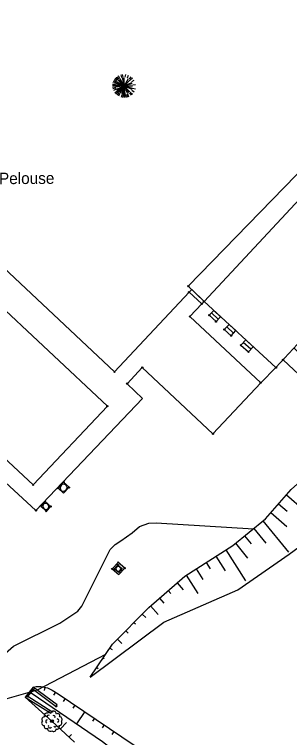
# Model space of a CAD drawing. Extents: x 344013 to 344423, y 298505 to 298795.
# Drawn here: x 344157.5 to 344180.9, y 298556.7 to 298618.3 of the extents above; entities that cross this region are included whole.
import ezdxf

# ---------------------------------------------------------------- set-up
doc = ezdxf.new("R2010")
doc.units = 0
for name, color, linetype in [('Default', 7, 'Continuous'), ('DH_CADRE -CARTOUCHE', 7, 'Continuous'), ('GO_MUR', 7, 'Continuous'), ('PC_CONCRETE', 7, 'Continuous'), ('PS_BOLT', 7, 'Continuous'), ('PS_CONST', 7, 'Continuous'), ('PS_DIM', 7, 'Continuous'), ('TOPO_COURBE NIVEAU', 7, 'Continuous'), ('TOPO_POINT', 7, 'Continuous'), ('TOPO_TALUS-TERRAIN NATUREL', 7, 'Continuous'), ('VOIRIE_ESPACE VERT', 7, 'Continuous')]:
    doc.layers.add(name, color=color, linetype=linetype)

# ---------------------------------------------------------------- blocks, each defined once
blk = doc.blocks.new('REG_INC')
at = {"layer": 'Default'}
for p, q in [((0, 1), (1, 1)), ((0, 0), (0, 1)), ((1, 1), (1, 0)), ((1, 0), (0, 0))]:
    blk.add_line(p, q, dxfattribs=at)
for centre, start, end in [((0.5, 0.498), 90.00577, 135.00577), ((0.5, 0.5), 45.00687, 90.00687), ((0.498, 0.5), 135.00554, 180.00554), ((0.501, 0.5), 180.00663, 225.00663), ((0.499, 0.498), 225.00686, 270.00686), ((0.499, 0.5), 270.00577, 315.00577), ((0.499, 0.499), 0.00663, 45.00663), ((0.501, 0.499), 315.00554, 0.00554)]:
    blk.add_arc(centre, 0.44, start, end, dxfattribs=at)
blk = doc.blocks.new('POINT_DISPLAY')
at = {"layer": 'Default'}
blk.add_circle((0, 0), 0.05, dxfattribs=at)
blk = doc.blocks.new('ARB1')
at = {"layer": 'Default'}
blk.add_circle((0, 0), 0.122, dxfattribs=at)
for centre, radius, start, end in [((-0.471, 0.503), 0.183, 53.95544, 222.20655), ((-0.153, 0.664), 0.211, 43.69255, 183.5969), ((0.139, 0.613), 0.241, 358.45835, 125.19284), ((0.501, 0.468), 0.183, 325.14445, 131.01755), ((-0.613, 0.139), 0.241, 88.45835, 215.19284), ((-0.373, -0.024), 0.149, 103.70924, 242.34652), ((-0.276, 0.37), 0.134, 52.43963, 209.54959), ((0.164, 0.38), 0.112, 330.58954, 133.71274), ((0.458, 0.052), 0.137, 276.62143, 88.96702), ((0.613, -0.139), 0.241, 268.45835, 35.19284), ((0.664, 0.153), 0.211, 313.69255, 93.5969), ((-0.664, -0.153), 0.211, 133.69255, 273.5969), ((-0.478, -0.443), 0.19, 155.22426, 300.93774), ((-0.139, -0.613), 0.241, 178.45835, 305.19284), ((-0.163, -0.42), 0.148, 159.53711, 338.16632), ((0.271, -0.38), 0.112, 210.58954, 13.71274), ((0.448, -0.483), 0.188, 243.13234, 33.02965), ((0.153, -0.664), 0.211, 223.69255, 3.5969)]:
    blk.add_arc(centre, radius, start, end, dxfattribs=at)
blk = doc.blocks.new('ARB2')
at = {"layer": 'Default'}
for p, q in [((-0.513, 0.525), (-0.688, 0.702)), ((-0.438, 0.589), (-0.588, 0.786)), ((-0.356, 0.642), (-0.481, 0.858)), ((-0.181, 0.716), (-0.244, 0.956)), ((-0.088, 0.736), (-0.119, 0.983)), ((0.106, 0.736), (0.144, 0.983)), ((0.287, 0.684), (0.388, 0.914)), ((0.456, 0.589), (0.612, 0.786)), ((0.531, 0.525), (0.706, 0.702)), ((-0.731, 0), (-0.981, 0)), ((-0.725, 0.1), (-0.969, 0.133)), ((-0.706, 0.195), (-0.944, 0.259)), ((-0.675, 0.286), (-0.9, 0.381)), ((-0.631, 0.373), (-0.844, 0.497)), ((-0.575, 0.453), (-0.775, 0.605)), ((0.65, 0.373), (0.862, 0.497)), ((0.744, 0.1), (0.987, 0.133)), ((-0.725, -0.1), (-0.969, -0.133)), ((-0.706, -0.195), (-0.944, -0.259)), ((-0.675, -0.287), (-0.9, -0.383)), ((-0.575, -0.455), (-0.775, -0.605)), ((-0.513, -0.527), (-0.688, -0.702)), ((-0.438, -0.591), (-0.588, -0.787)), ((0.456, -0.591), (0.612, -0.787)), ((0.531, -0.527), (0.706, -0.702)), ((0.65, -0.373), (0.862, -0.498)), ((0.725, -0.195), (0.963, -0.259)), ((-0.356, -0.644), (-0.481, -0.859)), ((-0.181, -0.717), (-0.244, -0.956)), ((-0.088, -0.737), (-0.119, -0.983)), ((0.013, -0.741), (0.013, -0.989)), ((0.106, -0.737), (0.144, -0.983)), ((0.2, -0.717), (0.263, -0.956)), ((0.287, -0.686), (0.388, -0.916))]:
    blk.add_line(p, q, dxfattribs=at)
for points in [[(-0.169, 0.677), (0.013, 0), (-0.6, 0.35)], [(0.013, 0.008), (0.013, 0), (-0.081, 0.695)], [(0.362, 0.608), (0.013, 0), (0.013, 0.702)], [(-0.487, -0.497), (0.013, 0), (-0.694, 0)], [(-0.688, 0.091), (0.013, 0), (-0.338, 0.608)], [(-0.638, -0.269), (0.013, 0), (-0.688, -0.092)], [(-0.487, 0.495), (0.013, 0), (-0.669, 0.181)], [(-0.419, 0.556), (0.013, 0), (-0.638, 0.269)], [(-0.169, -0.678), (0.013, 0), (-0.6, -0.352)], [(-0.544, -0.428), (0.013, 0), (-0.338, -0.608)], [(-0.081, -0.695), (0.013, 0), (-0.419, -0.558)], [(0.013, -0.702), (0.013, 0), (0, 0)], [(0.656, 0.269), (0.013, 0), (0.506, 0.495)], [(0.688, 0.181), (0.013, 0), (0.713, 0)], [(0.438, -0.558), (0.013, 0), (0.656, -0.269)], [(0.506, -0.497), (0.013, 0), (0.688, -0.181)], [(0.1, -0.695), (0.013, 0), (0.281, -0.648)], [(0.019, 0), (0.013, 0), (0.013, -0.009)]]:
    blk.add_lwpolyline(points, dxfattribs=at)

msp = doc.modelspace()

# ---------------------------------------------------------------- linework, layer by layer
at = {"layer": 'DH_CADRE -CARTOUCHE'}
for points in [[(344159.085, 298578.25), (344123.824, 298611.129), (344130.237, 298617.899), (344165.405, 298584.943)], [(344173.637, 298593.851), (344189.896, 298611.294), (344195.985, 298605.701), (344179.76, 298588.225)]]:
    msp.add_lwpolyline(points, close=True, dxfattribs=at)
at = {"layer": 'GO_MUR'}
msp.add_lwpolyline([(344160.686, 298558.935), (344158.641, 298560.224), (344159.117, 298560.832), (344161.054, 298559.39), (344161.144, 298559.51), (344159.089, 298561.039), (344158.42, 298560.186), (344160.606, 298558.808)], close=True, dxfattribs=at)
at = {"layer": 'PS_BOLT'}
for points in [[(344173.637, 298593.851), (344172.292, 298595.161), (344185.567, 298608.8), (344198.259, 298622.397), (344163.217, 298655.561), (344163.898, 298656.291), (344171.693, 298664.218), (344209.192, 298629.258), (344201.744, 298621.299), (344205.95, 298617.379), (344203.771, 298607.721), (344197.46, 298609.156), (344192.341, 298613.899), (344190.988, 298612.393), (344196.963, 298606.8), (344195.985, 298605.701)], [(344173.444, 298593.641), (344172.427, 298592.568), (344178.462, 298586.939), (344174.396, 298582.587), (344168.376, 298588.228), (344167.085, 298586.853), (344168.386, 298585.586), (344159.324, 298576.069), (344121.411, 298611.054), (344130.716, 298620.945), (344149.461, 298603.379), (344147.717, 298601.519)], [(344149.461, 298603.379), (344166.011, 298587.87), (344172.356, 298594.641)], [(344173.444, 298593.641), (344172.356, 298594.641)], [(344179.76, 298588.225), (344178.462, 298586.939), (344172.427, 298592.568), (344173.444, 298593.641), (344173.637, 298593.851)], [(344181.304, 298589.888), (344183.07, 298588.205), (344182.156, 298587.216), (344180.365, 298588.877)]]:
    msp.add_lwpolyline(points, dxfattribs=at)
msp.add_lwpolyline([(344166.885, 298571.16), (344166.324, 298571.64), (344165.819, 298571.088), (344166.38, 298570.609)], close=True, dxfattribs=at)
at = {"layer": 'PS_DIM'}
for points in [[(344172.585, 298594.876), (344172.356, 298594.641), (344173.444, 298593.641), (344173.637, 298593.851)], [(344175.045, 298592.557), (344174.66, 298592.137), (344174.086, 298592.684), (344174.462, 298593.093)], [(344175.763, 298591.898), (344175.363, 298591.462), (344175.943, 298590.936), (344176.339, 298591.368)], [(344177.19, 298590.587), (344176.772, 298590.132), (344177.42, 298589.564), (344177.824, 298590.004)]]:
    msp.add_lwpolyline(points, close=True, dxfattribs=at)
for points in [[(344174.852, 298592.347), (344174.274, 298592.889)], [(344176.141, 298591.152), (344175.563, 298591.68)], [(344177.622, 298589.784), (344176.981, 298590.359)]]:
    msp.add_lwpolyline(points, dxfattribs=at)
at = {"layer": 'TOPO_COURBE NIVEAU'}
for points in [[(344156.256, 298563.524), (344157.409, 298564.509), (344161.369, 298566.478), (344162.88, 298567.483), (344163.228, 298567.922), (344165.643, 298572.732), (344166.068, 298573.157), (344166.564, 298573.494), (344167.517, 298574.16), (344168.147, 298574.694), (344168.934, 298574.993), (344169.564, 298575.023), (344177.835, 298574.512)], [(344144.559, 298543.398), (344145.126, 298543.758), (344146.164, 298544.291), (344147.173, 298545.407), (344147.575, 298546.106), (344147.955, 298547.238), (344148.408, 298549.983), (344148.576, 298551.974), (344149.201, 298553.647), (344150.556, 298555.627), (344153.701, 298558.494), (344155.669, 298559.733), (344159.453, 298560.805), (344165.265, 298563.828)]]:
    msp.add_lwpolyline(points, dxfattribs=at)
at = {"layer": 'TOPO_TALUS-TERRAIN NATUREL'}
for p, q in [((344180.646, 298577.395), (344182.159, 298576.077)), ((344179.989, 298576.641), (344180.708, 298576.015)), ((344179.332, 298575.887), (344180.697, 298574.698)), ((344178.64, 298575.169), (344180.813, 298572.505)), ((344177.865, 298574.537), (344178.897, 298573.272)), ((344177.09, 298573.904), (344177.634, 298573.237)), ((344176.315, 298573.272), (344177.349, 298572.004)), ((344175.491, 298572.706), (344177.166, 298570.089)), ((344174.649, 298572.167), (344175.444, 298570.924)), ((344173.806, 298571.627), (344174.146, 298571.096)), ((344172.964, 298571.088), (344173.545, 298570.18)), ((344172.121, 298570.549), (344173.115, 298568.997)), ((344171.352, 298569.912), (344171.866, 298569.316)), ((344170.595, 298569.258), (344170.815, 298569.004)), ((344169.838, 298568.605), (344170.214, 298568.169)), ((344169.081, 298567.951), (344169.723, 298567.207)), ((344168.368, 298567.25), (344168.668, 298566.955)), ((344167.667, 298566.537), (344167.795, 298566.411)), ((344166.965, 298565.823), (344167.184, 298565.608)), ((344166.264, 298565.11), (344166.638, 298564.742)), ((344165.62, 298564.35), (344165.805, 298564.224)), ((344165.058, 298563.523), (344165.137, 298563.469)), ((344164.496, 298562.695), (344164.631, 298562.603)), ((344159.089, 298561.039), (344159.089, 298561.039)), ((344160.076, 298561.009), (344160.015, 298560.736)), ((344160.985, 298560.609), (344160.827, 298560.347)), ((344161.821, 298560.061), (344161.648, 298559.805)), ((344162.65, 298559.502), (344162.476, 298559.244)), ((344163.478, 298558.942), (344162.781, 298557.91)), ((344164.307, 298558.382), (344164.132, 298558.123)), ((344161.415, 298557.468), (344161.937, 298558.011)), ((344165.136, 298557.822), (344164.96, 298557.562)), ((344165.964, 298557.262), (344165.786, 298556.998)), ((344162.137, 298556.776), (344162.36, 298557.008))]:
    msp.add_line(p, q, dxfattribs=at)
for points in [[(344163.934, 298561.868), (344165.849, 298564.688), (344168.923, 298567.814), (344171.996, 298570.469), (344176.091, 298573.09), (344178.872, 298575.358), (344181.046, 298577.856), (344183.915, 298580.416), (344184.947, 298581.398), (344185.091, 298582.452), (344184.802, 298583.514), (344186.691, 298584.063), (344189.735, 298586.719), (344192.676, 298590.389), (344195.465, 298594.065), (344199.099, 298597.718), (344203.435, 298602.18), (344207.43, 298606.195), (344211.519, 298610.49), (344214.324, 298613.364), (344217.026, 298616.042), (344219.477, 298617.84), (344221.365, 298618.23), (344223.701, 298617.841)], [(344163.934, 298561.868), (344170.201, 298566.564), (344176.522, 298569.299), (344180.879, 298572.338), (344183.313, 298574.136), (344185.048, 298576.477), (344188.051, 298580.099), (344191.638, 298583.956), (344195.571, 298587.909), (344198.338, 298590.807), (344202.379, 298595.055), (344209.468, 298599.999), (344216.32, 298605.698), (344221.544, 298609.146), (344226.03, 298610.067), (344230.196, 298608.376), (344234.376, 298605.349), (344238.337, 298601.801), (344242.051, 298598.625), (344245.256, 298595.883), (344247.329, 298593.914), (344248.413, 298593.093)], [(344159.089, 298561.039), (344159.354, 298561.091), (344159.742, 298561.084), (344160.297, 298560.96), (344160.706, 298560.777), (344161.231, 298560.46), (344172.069, 298553.135), (344173.202, 298552.277), (344176.155, 298549.708), (344180.474, 298545.354), (344182.152, 298543.854), (344182.779, 298543.428), (344183.25, 298543.23), (344183.942, 298543.143), (344184.794, 298543.131), (344197.63, 298543.79), (344202.568, 298544.192), (344226.369, 298544.819)], [(344162.596, 298556.335), (344160.685, 298558.13), (344158.42, 298560.186)], [(344158.923, 298560.537), (344164.997, 298556.401), (344169.095, 298553.232), (344172.662, 298550.66), (344176.659, 298547.676), (344178.472, 298545.954), (344180.609, 298543.896), (344181.623, 298542.715), (344182.451, 298541.471), (344182.948, 298539.664)]]:
    msp.add_lwpolyline(points, dxfattribs=at)

# ---------------------------------------------------------------- block references
at = {"layer": 'PC_CONCRETE'}
for p, xscale, yscale, rotation in [((344161.685, 298578.474), 0.7012818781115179, 0.640469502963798, -133.01802000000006), ((344160.582, 298576.404), 0.632832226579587, 0.5487555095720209, 138.24152999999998), ((344166.307, 298571.423), 0.452665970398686, 0.46586556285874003, -129.82707000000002)]:
    msp.add_blockref('REG_INC', p, dxfattribs=dict(at, xscale=xscale, yscale=yscale, rotation=rotation))
at = {"layer": 'TOPO_POINT'}
for p in [(344166.826, 298612.196), (344172.292, 298595.161), (344172.356, 298594.641), (344173.444, 298593.641), (344173.637, 298593.851), (344173.637, 298593.851), (344172.427, 298592.568), (344174.086, 298592.684), (344174.66, 298592.137), (344175.363, 298591.462), (344175.943, 298590.936), (344176.772, 298590.132), (344177.42, 298589.564), (344180.363, 298588.88), (344166.011, 298587.87), (344168.376, 298588.228), (344179.76, 298588.225), (344167.085, 298586.853), (344167.086, 298586.876), (344178.462, 298586.939), (344165.405, 298584.943), (344174.396, 298582.587), (344159.085, 298578.25), (344161.685, 298578.474), (344162.133, 298578.015), (344161.207, 298577.961), (344160.11, 298576.825), (344160.582, 298576.404), (344159.324, 298576.069), (344160.197, 298576.012), (344166.307, 298571.423), (344166.324, 298571.64), (344165.819, 298571.088), (344166.017, 298571.076), (344166.885, 298571.16), (344159.117, 298560.832), (344158.641, 298560.224), (344158.923, 298560.537), (344160.686, 298558.935), (344161.054, 298559.39), (344160.685, 298558.13)]:
    msp.add_blockref('POINT_DISPLAY', p, dxfattribs=at)
at = {"layer": 'VOIRIE_ESPACE VERT'}
for name, p in [('ARB2', (344166.826, 298612.196)), ('ARB1', (344160.685, 298558.13))]:
    msp.add_blockref(name, p, dxfattribs=at)

# ---------------------------------------------------------------- texts
at = {"layer": 'PS_CONST'}
msp.add_text('Pelouse', height=0.9758, rotation=0.36653, dxfattribs=at).set_placement((344156.182, 298603.834))

doc.saveas('drawing.dxf')
